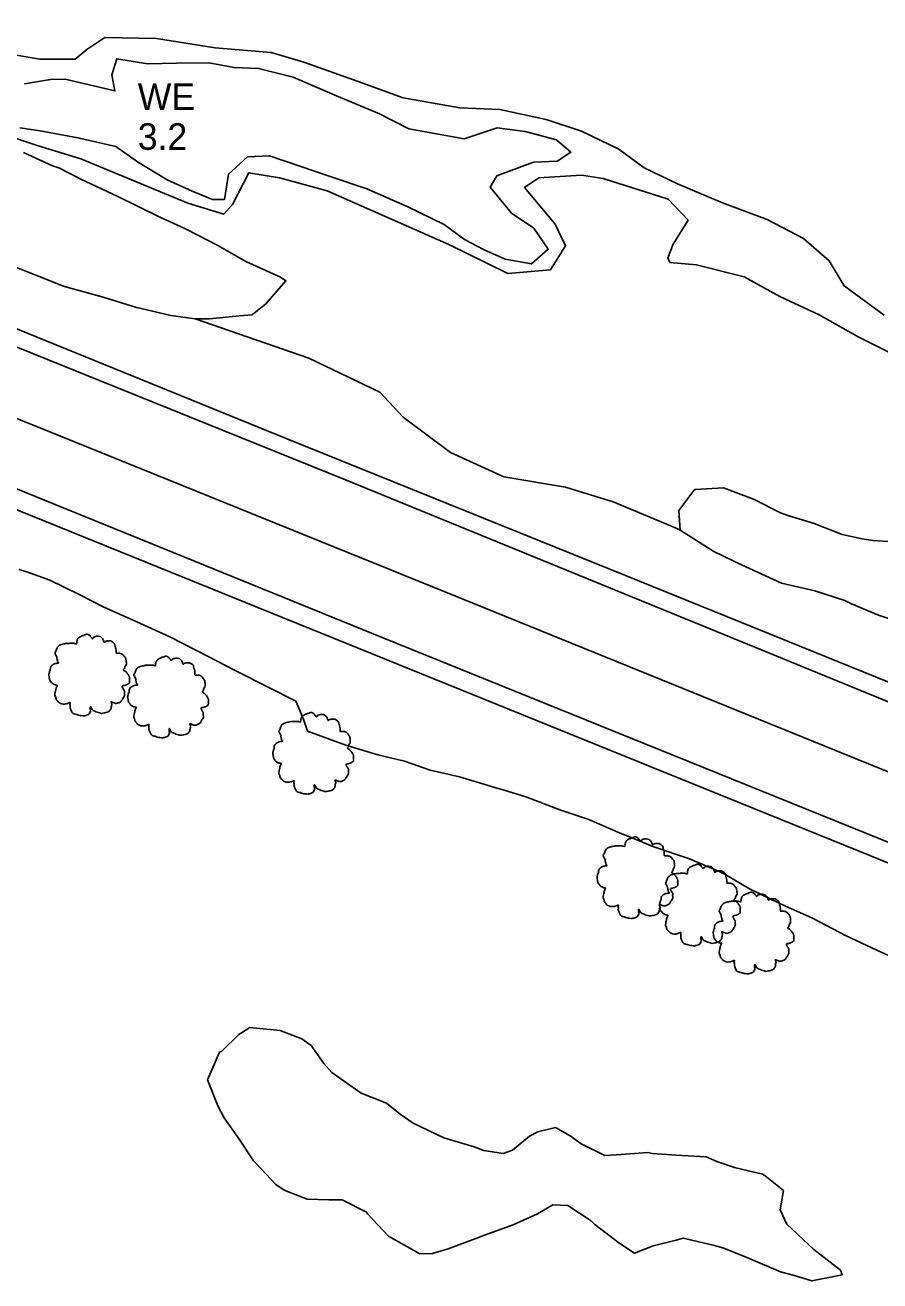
# Model space of a CAD drawing. Extents: x 2160437 to 2172832, y 205694 to 212444.
# Drawn here: x 2166777.9 to 2166938.6, y 208876.7 to 209112.8 of the extents above; entities that cross this region are included whole.
import ezdxf

# ---------------------------------------------------------------- set-up
doc = ezdxf.new("R2010")
doc.units = 0
for name, color, linetype in [('RD_EX_H2O_Pond', 7, 'Continuous'), ('RD_EX_H2O_txCode', 7, 'Continuous'), ('RD_EX_LaneStripe', 7, 'Continuous'), ('RD_EX_Road', 7, 'Continuous'), ('RD_EX_VEG', 7, 'Continuous'), ('RD_EX_VEG_ShrubLine', 7, 'Continuous'), ('RD_EX_VEG_TreeLine', 7, 'Continuous')]:
    doc.layers.add(name, color=color, linetype=linetype)

# ---------------------------------------------------------------- blocks, each defined once
blk = doc.blocks.new('T2')
at = {"layer": 'RD_EX_VEG'}
for points in [[(0.05, 7.21), (-0.25, 7.24), (-0.57, 7.14), (-0.82, 7.04), (-1.05, 6.96), (-1.27, 6.86), (-1.57, 6.69), (-1.8, 6.49), (-1.92, 6.24), (-1.97, 6.01), (-2.02, 5.74), (-2.02, 5.56), (-2.15, 5.54), (-2.3, 5.56), (-2.55, 5.64), (-2.8, 5.64), (-3.05, 5.64), (-3.4, 5.61), (-3.75, 5.61), (-4.02, 5.56), (-4.35, 5.51), (-4.72, 5.39), (-5.07, 5.26), (-5.37, 5.01), (-5.62, 4.54), (-5.75, 4.19), (-5.9, 3.94), (-5.75, 3.49), (-5.57, 3.14), (-5.55, 2.94), (-5.47, 2.52), (-5.37, 2.29), (-5.25, 2.09), (-5.32, 2.07), (-5.7, 2.02), (-6, 1.92), (-6.42, 1.69), (-6.64, 1.47), (-6.74, 1.14), (-6.77, 0.79), (-6.87, 0.59), (-6.94, 0.32), (-6.97, 0.24), (-7.02, -0.08), (-6.92, -0.53), (-6.89, -0.88), (-6.77, -1.11), (-6.62, -1.28), (-6.44, -1.53), (-6.05, -1.76), (-5.72, -1.86), (-5.52, -1.88), (-5.7, -2.38), (-5.75, -2.73), (-5.87, -3.13), (-5.87, -3.21), (-5.92, -3.68), (-5.77, -4.01), (-5.7, -4.38), (-5.52, -4.61), (-5.25, -4.91), (-4.92, -5.13), (-4.42, -5.26), (-4.02, -5.23), (-3.45, -5.06), (-3.2, -4.98), (-3.22, -5.16), (-3.2, -5.53), (-3.2, -5.96), (-3.05, -6.28), (-2.95, -6.56), (-2.8, -6.81), (-2.47, -7.03), (-2.07, -7.11), (-1.65, -7.26), (-1.2, -7.33), (-0.7, -7.36), (-0.1, -7.21), (0.18, -7.08), (0.28, -6.91), (0.48, -6.53), (0.43, -6.31), (0.45, -5.71), (0.55, -5.88), (0.73, -6.23), (1.23, -6.53), (1.63, -6.71), (2.1, -6.86), (2.4, -6.93), (2.88, -6.86), (3.25, -6.78), (3.63, -6.66), (3.93, -6.38), (4.1, -6.11), (4.15, -5.83), (4.23, -5.46), (4.28, -5.28)], [(4.28, -5.28), (4.2, -5.11), (4.15, -4.86), (4.23, -4.88), (4.4, -4.93), (4.68, -5.06), (4.9, -5.13), (5.23, -5.11), (5.5, -5.01), (5.95, -4.73), (6.22, -4.26), (6.5, -3.86), (6.57, -3.53), (6.52, -3.31), (6.5, -2.81), (6.3, -2.56), (6.25, -2.43), (6.15, -2.03), (6.22, -1.98), (6.5, -1.93), (6.87, -1.81), (7.15, -1.68), (7.37, -1.51), (7.45, -1.28), (7.42, -0.88), (7.47, -0.48), (7.4, -0.33), (7.3, -0.18), (7.22, 0.02), (7.07, 0.17), (6.97, 0.32), (6.87, 0.42), (6.75, 0.57), (6.57, 0.69), (6.42, 0.74), (6.37, 0.89), (6.52, 1.09), (6.57, 1.19), (6.6, 1.42), (6.82, 1.77), (6.87, 2.17), (6.82, 2.59), (6.77, 2.87), (6.62, 3.14), (6.42, 3.39), (6.3, 3.56), (6.12, 3.69), (5.8, 3.81), (5.55, 3.86), (5.2, 3.86), (5, 3.91), (5.03, 3.96), (5.03, 4.11), (5.03, 4.39), (4.95, 4.84), (4.8, 5.34), (4.8, 5.36), (4.7, 5.61), (4.48, 5.81), (4.3, 5.91), (4.1, 6.04), (3.85, 6.06), (3.55, 6.06), (3.28, 6.01), (3.08, 5.91), (2.9, 5.79), (2.83, 5.94), (2.73, 6.24), (2.68, 6.39), (2.53, 6.56), (2.3, 6.76), (1.85, 6.89), (1.23, 6.81), (0.93, 6.61), (0.78, 6.44), (0.73, 6.56), (0.53, 6.76), (0.43, 6.94), (0.25, 7.06), (0.1, 7.16), (0, 7.21)]]:
    blk.add_spline(points, degree=3, dxfattribs=at)

msp = doc.modelspace()

# ---------------------------------------------------------------- linework, layer by layer
at = {"layer": 'RD_EX_H2O_Pond'}
msp.add_lwpolyline([(2166776.92, 209093.47), (2166780.77, 209092.9), (2166787.85, 209091.62), (2166794.97, 209090), (2166799.06, 209087.09), (2166804.62, 209083.69), (2166809.35, 209081.6), (2166813.17, 209080), (2166815.42, 209080.03), (2166816.16, 209084.8), (2166819.75, 209088.03), (2166823.83, 209088.24), (2166835.27, 209084.35), (2166842.19, 209082.02), (2166849.77, 209078.7), (2166856.7, 209075.3), (2166860.54, 209072.5), (2166864.19, 209070.53), (2166868.19, 209068.77), (2166873.1, 209067.91), (2166876.27, 209070.65), (2166873.59, 209074.61), (2166869.34, 209077.47), (2166865.33, 209082.35), (2166866.59, 209084.45), (2166873.5, 209087.04), (2166877.94, 209087.21), (2166880.52, 209088.91), (2166877.84, 209091.24), (2166871.94, 209092.8), (2166866.66, 209093.52), (2166860.47, 209091.41), (2166850.06, 209093.33), (2166844.55, 209096.15), (2166836.48, 209099.5), (2166828.3, 209103.03), (2166821.82, 209104.67), (2166817.21, 209104.82), (2166812.46, 209105.74), (2166806.37, 209105.64), (2166800.91, 209105.56), (2166795.14, 209106.44), (2166794.21, 209103.43), (2166794.78, 209100.43), (2166785.46, 209102.67), (2166782.67, 209102.57), (2166777.82, 209101.78)], dxfattribs=at)
at = {"layer": 'RD_EX_LaneStripe'}
msp.add_lwpolyline([(2166025.36, 209344.25), (2166108.97, 209310.08), (2166179, 209281.39), (2166248.32, 209253.24), (2166322.6, 209223.02), (2166428.12, 209180.09), (2166499.44, 209151.2), (2166571.15, 209122.03), (2166642.26, 209093.12), (2166713.47, 209064.17), (2166784.54, 209035.5), (2166854.09, 209007.34), (2166996.21, 208949.61), (2167074.48, 208917.74), (2167146.55, 208888.33)], dxfattribs=at)
at = {"layer": 'RD_EX_Road'}
for points in [[(2166026.17, 209360.72), (2166104.45, 209329.24), (2166218.97, 209282.28), (2166318.19, 209241.85), (2166429.86, 209196.42), (2166532.44, 209155.56), (2166615.15, 209121.73), (2166718.37, 209079.44), (2166758.57, 209062.93), (2166826.99, 209035.09), (2166891.12, 209009.17), (2166956.69, 208982.6), (2167013.45, 208959.75), (2167046.21, 208945.39), (2167108.06, 208919.54), (2167125.82, 208911.38), (2167128.12, 208905.84)], [(2166024.71, 209357.76), (2166117.95, 209319.57), (2166186.21, 209291.8), (2166298.24, 209246.06), (2166371.62, 209216.13), (2166463.14, 209179.26), (2166548.9, 209144.32), (2166648.16, 209104.03), (2166717.23, 209075.95), (2166755.68, 209060.57), (2166838.17, 209027.28), (2166917.84, 208994.71), (2167010.25, 208956.85), (2167067.32, 208932.42), (2167128.12, 208905.84), (2167149.74, 208896.27)], [(2166015.83, 209334.81), (2166072.81, 209311.37), (2166182.98, 209266.77), (2166282.53, 209226.31), (2166401.71, 209177.97), (2166514.59, 209132.05), (2166616.41, 209090.49), (2166709.27, 209052.8), (2166770.4, 209027.97), (2166845.06, 208997.67), (2166946.51, 208956.61), (2167027.58, 208923.96), (2167082.42, 208902.57), (2167142.85, 208879.55)], [(2166014.65, 209331.72), (2166089.07, 209301.24), (2166186.34, 209261.39), (2166293.04, 209218.16), (2166386.32, 209180.32), (2166516.17, 209127.72), (2166639.01, 209076.95), (2166708.04, 209049.04), (2166753.09, 209031.03), (2166819.33, 209004.22), (2166878.6, 208980.23), (2166936.73, 208956.62), (2166973.88, 208941.43), (2167018.87, 208923.18), (2167070.62, 208903.38), (2167105.14, 208890.26), (2167142.48, 208878.61)]]:
    msp.add_lwpolyline(points, dxfattribs=at)
at = {"layer": 'RD_EX_VEG_ShrubLine'}
for points in [[(2166939.44, 209058.28), (2166931.9, 209063.77), (2166929.11, 209068.46), (2166924.23, 209072.67), (2166917.45, 209076.25), (2166909.03, 209079.39), (2166900.56, 209082.99), (2166894.33, 209086), (2166889.51, 209089.5), (2166882.55, 209092.85), (2166875.89, 209095.06), (2166867.14, 209096.92), (2166859.64, 209097.27), (2166848.96, 209099.14), (2166840.51, 209102.22), (2166830.32, 209105.85), (2166824.16, 209107.66), (2166813.67, 209108.56), (2166802.61, 209110.28), (2166792.91, 209110.45), (2166789.54, 209108.24), (2166787.32, 209106.38), (2166780.67, 209106.41), (2166773.72, 209107.58)], [(2166773.83, 209092.32), (2166780.16, 209090.2), (2166788.4, 209087.64), (2166808.49, 209079.32), (2166815.27, 209077.24), (2166816.9, 209079.05), (2166820, 209085.06), (2166825.73, 209084.08), (2166834.73, 209081.67), (2166857.6, 209071.53), (2166868.65, 209066.08), (2166876.69, 209066.78), (2166879.5, 209071.31), (2166877.54, 209075.37), (2166877.54, 209075.37), (2166871.83, 209082.27), (2166874.47, 209084.12), (2166882.55, 209084.62), (2166886.62, 209083.96), (2166898.8, 209080.05), (2166902.55, 209076.1), (2166899.77, 209071.63), (2166898.77, 209069.03), (2166899.14, 209068.18), (2166904.16, 209067.71), (2166913.1, 209065.45), (2166919.79, 209061.79), (2166927.18, 209058.31), (2166934.67, 209054.1), (2166947.01, 209047.93)], [(2166901.09, 209017.83), (2166900.35, 209018.2), (2166888.46, 209023.16), (2166879.49, 209025.93), (2166867.92, 209027.88), (2166857.9, 209032.43), (2166849.02, 209039.08), (2166844.6, 209043.77), (2166831.26, 209050.2), (2166809.89, 209057.6)], [(2166776.7, 209010.41), (2166778.04, 209010.06), (2166782.54, 209008.45), (2166788.05, 209005.76), (2166792.73, 209003.32), (2166798.23, 209000.88), (2166802.36, 208999.01), (2166805.1, 208997.76), (2166812.48, 208993.98), (2166817.27, 208991.49), (2166823.76, 208988.23), (2166828.83, 208985.67), (2166830.28, 208982.27), (2166831.01, 208980.04), (2166838.21, 208977.39), (2166838.21, 208977.39), (2166844.2, 208975.61), (2166849.24, 208974.37), (2166854.08, 208972.68), (2166854.08, 208972.68), (2166859.56, 208971.43), (2166866.85, 208969.24), (2166867.8, 208969), (2166872.22, 208967.61), (2166878.43, 208965.23), (2166883.9, 208963.43), (2166889.35, 208961.02), (2166893.24, 208959.44), (2166895.92, 208958.34), (2166902.84, 208956.01), (2166907.38, 208954.07), (2166909.34, 208953.18), (2166914.12, 208950.39), (2166919.68, 208947.68), (2166920.76, 208947.19), (2166925.95, 208944.89), (2166932.3, 208941.57), (2166938.03, 208938.84), (2166941.86, 208937.11)]]:
    msp.add_lwpolyline(points, dxfattribs=at)
msp.add_lwpolyline([(2166820.19, 208924.32), (2166818.43, 208923.19), (2166818.09, 208922.97), (2166814.87, 208919.88), (2166814.45, 208919.64), (2166812.23, 208914.48), (2166812.23, 208914.48), (2166814.12, 208909.57), (2166815.34, 208907.33), (2166818.18, 208903.3), (2166820.88, 208899.21), (2166821.3, 208898.77), (2166825.08, 208894.75), (2166826.61, 208893.74), (2166830.94, 208892.02), (2166835.01, 208891.92), (2166837.55, 208891.89), (2166842.11, 208889.57), (2166842.29, 208889.29), (2166846.23, 208885.07), (2166846.23, 208885.07), (2166852.12, 208881.72), (2166854.53, 208881.8), (2166857.47, 208882.65), (2166862.65, 208884.6), (2166864.1, 208885.18), (2166869.69, 208887.19), (2166869.69, 208887.19), (2166874.26, 208889.29), (2166877.14, 208890.98), (2166879.94, 208890.83), (2166884.31, 208887.97), (2166885.05, 208887.26), (2166889.52, 208883.79), (2166892.51, 208881.88), (2166895.99, 208883.22), (2166900.29, 208884.32), (2166901.64, 208884.71), (2166907.25, 208883.34), (2166909.31, 208882.78), (2166913.9, 208880.95), (2166919.96, 208878.38), (2166922.34, 208877.73), (2166925.84, 208876.65), (2166931.53, 208877.8), (2166931.24, 208878.68), (2166926.22, 208882.58), (2166926.22, 208882.58), (2166921.15, 208887.31), (2166919.88, 208890.01), (2166920.53, 208893.64), (2166917.05, 208896.4), (2166916.56, 208896.69), (2166911.28, 208897.96), (2166907.94, 208899.11), (2166905.95, 208899.95), (2166900.33, 208900.32), (2166895.9, 208900.59), (2166895, 208900.81), (2166889.08, 208900.38), (2166886.9, 208900.25), (2166882.47, 208902.45), (2166880.41, 208903.94), (2166877.61, 208905.47), (2166874.32, 208904.66), (2166872.77, 208903.86), (2166869.52, 208901.23), (2166867.79, 208900.58), (2166864.14, 208901.18), (2166862.34, 208901.87), (2166856.61, 208903.54), (2166856.61, 208903.54), (2166850.85, 208906.34), (2166848.42, 208908.01), (2166845.88, 208910.09), (2166841.12, 208911.95), (2166841.12, 208911.95), (2166835.59, 208915.83), (2166834.05, 208917.52), (2166831.67, 208920.91), (2166829.94, 208922.19), (2166825.85, 208923.74)], close=True, dxfattribs=at)
at = {"layer": 'RD_EX_VEG_TreeLine'}
for points in [[(2166777.6, 209088.84), (2166783.07, 209086.36), (2166784.25, 209085.95), (2166788.4, 209083.81), (2166795.19, 209080.67), (2166802.87, 209076.87), (2166808.09, 209074.5), (2166810.26, 209073.38), (2166814.25, 209071.32), (2166819.44, 209068.34), (2166825.9, 209065.41), (2166826.96, 209064.74), (2166823.19, 209060.41), (2166820.63, 209058.33), (2166818.17, 209058.14), (2166812.55, 209057.58), (2166809.89, 209057.6), (2166805.3, 209058.19), (2166798.66, 209059.77), (2166792.6, 209061.66), (2166785.73, 209063.53), (2166785.13, 209063.74), (2166779.9, 209065.8), (2166775.03, 209067.7)], [(2166944.98, 208999.64), (2166938.37, 209001.83), (2166933.31, 209004), (2166932.02, 209004.59), (2166926.42, 209006.39), (2166920.12, 209007.88), (2166912.58, 209011.3), (2166907.43, 209013.83), (2166901.09, 209017.83), (2166900.83, 209021.5), (2166903.66, 209025.26), (2166903.88, 209025.47), (2166909.19, 209025.8), (2166914.89, 209023.65), (2166919.96, 209021.1), (2166921.3, 209020.61), (2166926.28, 209019.1), (2166931.56, 209017.01), (2166935.3, 209016.19), (2166937.29, 209015.91), (2166943.14, 209015.49)]]:
    msp.add_lwpolyline(points, dxfattribs=at)

# ---------------------------------------------------------------- block references
at = {"layer": 'RD_EX_VEG', "xscale": 1.0499999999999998, "yscale": 1.0499999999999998}
for p in [(2166789.73, 208990.65), (2166804.56, 208986.53), (2166831.84, 208975.94), (2166892.81, 208952.55), (2166904.55, 208947.4), (2166914.63, 208942.14)]:
    msp.add_blockref('T2', p, dxfattribs=at)

# ---------------------------------------------------------------- texts
at = {"layer": 'RD_EX_H2O_txCode'}
for s, p in [('WE', (2166799.09, 209096.85)), ('3.2', (2166799.09, 209089.35))]:
    msp.add_text(s, height=5, dxfattribs=at).set_placement(p)

doc.saveas('drawing.dxf')
